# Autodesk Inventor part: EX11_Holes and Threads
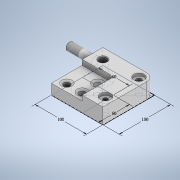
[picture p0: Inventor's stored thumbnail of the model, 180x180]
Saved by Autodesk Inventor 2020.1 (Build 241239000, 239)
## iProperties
Created: 2019-10
Part Number: EX11_Holes and Threads
Material: Generic
Document SubType Name: Modeling
Designer: Synergysoft Dell02
Density: 1 g/cm^3
Appearance: Default
Author: Synergysoft Dell02
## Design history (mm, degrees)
sketch "Sketch1"
  geometry: L1 (50, -50)-(-50, -50); L2 (-50, -50)-(-50, 50); L3 (-50, 50)-(50, 50); L4 (50, 50)-(50, -50); L5 (50, -50)-(-50, 50); L6 (-50, -50)-(50, 50); L7 (50, 50)-(-10, 50); L8 (-10, 50)-(-10, -10); L9 (-10, -10)-(50, -10); L10 (50, -10)-(50, 50); 3 further points
  constraints: 20 end point, 4 parallel, 2 horizontal, 2 midpoint, 2 perpendicular
  dimensions: "d0" = 100 distance of L2.end L3.end; "d1" = 100 distance of L1.end L2.end; "d2" = 60 distance of L9.end L8.end; "d3" = 60 distance of L8.end L7.end
extrude "Extrusion1" new body sketch "Sketch1" distance "d4" = 30; taper "d5" = 0 deg
extrude "Extrusion2" join sketch "Sketch1" distance "d6" = 20; taper "d7" = 0 deg
sketch "Sketch2"
  geometry: L1 (0, 0)-(0, 30) reference; L2 (0, 0)-(100, 0) reference; C1 r 7.5 at (15, 15); 1 further point
  constraints: 1 centre point
  dimensions: "d8" = 15 diameter of C1; "d9" = 15 distance from line of C1.centre L1; "d10" = 15 distance from line of L2 C1.centre
extrude "Extrusion3" join sketch "Sketch2" distance "d11" = 50; taper "d12" = 0 deg
fillet "Fillet1" dims "d13" = 15
sketch "Sketch3"
  geometry: L1 (-50, 50)-(-50, 10) reference; L2 (35, 50)-(-50, 50) reference; 2 further points
  dimensions: "d14" = 20 distance from line of L1 point (-30, 30); "d15" = 20 distance from line of L2 point (-30, 30)
hole "Hole1" sketch "Sketch3" at (-30, 30) diameter "d16" = 15; stored, may be unused: countersink angle "d20" = 90 deg, drill point angle "d22" = 118 deg; dims "d17" = 6, "d18" = 4, "d19" = 2, "d21" = 20
sketch "Sketch4"
  geometry: A1 r 15 centre (35, 35) between (50, 35) and (35, 50) reference; 2 further points
  constraints: 1 coincident
hole "Hole2" sketch "Sketch4" at (35, 35) diameter "d23" = 10; stored, may be unused: countersink angle "d27" = 90 deg, drill point angle "d29" = 118 deg; dims "d24" = 6, "d25" = 20, "d26" = 5, "d28" = 20
sketch "Sketch5"
  geometry: L1 (-50, 10)-(10, 10) reference; L2 (10, 10)-(10, -50) reference; L3 (-50, -50)-(10, -50) reference; L4 (-50, 10)-(-50, -50) reference; 4 further points
  dimensions: "d30" = 15 distance from line of L1 point (-5, -5); "d31" = 15 distance from line of L2 point (-5, -5); "d32" = 15 distance from line of L2 point (-5, -35); "d33" = 15 distance from line of L3 point (-5, -35); "d34" = 15 distance from line of L4 point (-35, -35); "d35" = 15 distance from line of L3 point (-35, -35)
hole "Hole3" sketch "Sketch5" at (-5, -5), (-5, -35), (-35, -35) diameter "d36" = 12; stored, may be unused: countersink angle "d40" = 118 deg, drill point angle "d42" = 118 deg; dims "d37" = 6, "d38" = 20, "d39" = 5, "d41" = 20
sketch "Sketch6"
  geometry: L1 (50, -50)-(50, 35) reference; L2 (10, -50)-(50, -50) reference; 2 further points
  dimensions: "d50" = 15 distance from line of L1 point (35, -30); "d51" = 20 distance from line of L2 point (35, -30)
hole "Hole4" sketch "Sketch6" at (35, -30) diameter "d43" = 8.376; stored, may be unused: countersink angle "d47" = 118 deg, drill point angle "d49" = 118 deg; dims "d44" = 15, "d45" = 20, "d46" = 5, "d48" = 27.3
thread "Thread1" dims "d52" = 20, "d53" = 0
thread "Thread2" dims "d54" = 25, "d55" = 25
chamfer "Chamfer1" distance "d56" = 1; stored, may be unused: second distance "d57" = 2, angle "d58" = 45 deg
body "Solid1"
